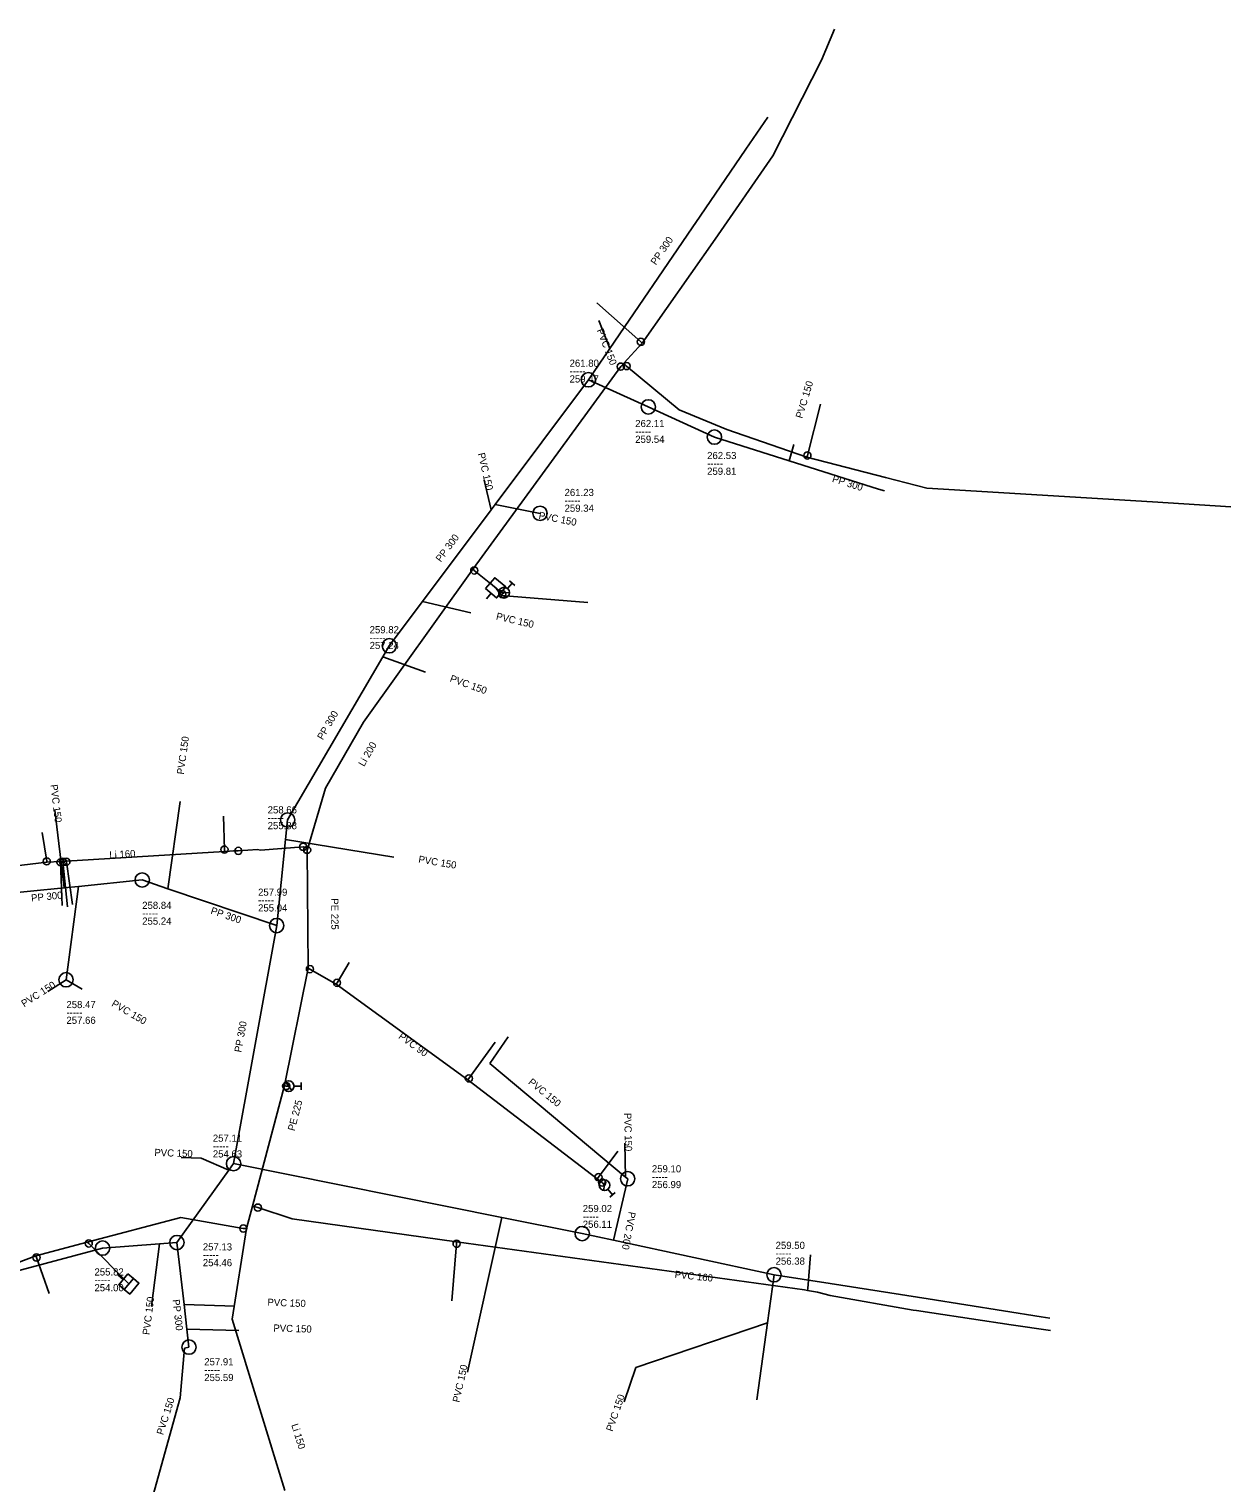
# Model space of a CAD drawing. Extents: x -771681 to -770485, y -1050143 to -1049574.
# Drawn here: x -770653 to -770485, y -1050034.6 to -1049831.5 of the extents above; entities that cross this region are included whole.
import ezdxf

# ---------------------------------------------------------------- set-up
doc = ezdxf.new("R2010")
doc.units = 0
doc.layers.add('Level 0', color=7, linetype='Continuous')

msp = doc.modelspace()

# ---------------------------------------------------------------- linework, layer by layer
at = {"layer": 'Level 0'}
for p, q in [((-770542.24, -1049835.81), (-770540.44, -1049831.47)), ((-770549.05, -1049849.2), (-770542.24, -1049835.81)), ((-770549.73, -1049843.76), (-770552.8, -1049848.25)), ((-770552.8, -1049848.25), (-770559.19, -1049857.6)), ((-770557.11, -1049860.82), (-770549.05, -1049849.2)), ((-770559.19, -1049857.6), (-770560.31, -1049859.24)), ((-770560.31, -1049859.24), (-770571.84, -1049876.11)), ((-770567.28, -1049875.34), (-770557.11, -1049860.82)), ((-770567.48, -1049875.17), (-770573.64, -1049869.74)), ((-770571.84, -1049876.11), (-770573.37, -1049872.19)), ((-770569.87, -1049878.17), (-770567.28, -1049875.34)), ((-770567.28, -1049875.34), (-770567.48, -1049875.17)), ((-770571.84, -1049876.11), (-770574.82, -1049880.47)), ((-770590.92, -1049906.89), (-770570.29, -1049878.63)), ((-770570.29, -1049878.63), (-770569.87, -1049878.17)), ((-770569.87, -1049878.17), (-770569.47, -1049878.55)), ((-770569.47, -1049878.55), (-770562.12, -1049884.66)), ((-770574.82, -1049880.47), (-770587.86, -1049897.9)), ((-770566.44, -1049884.26), (-770574.82, -1049880.47)), ((-770557.2, -1049888.48), (-770566.44, -1049884.26)), ((-770562.12, -1049884.66), (-770555.49, -1049887.4)), ((-770544.21, -1049891.04), (-770542.38, -1049883.87)), ((-770555.49, -1049887.4), (-770544.27, -1049891.28)), ((-770546.78, -1049891.78), (-770557.2, -1049888.48)), ((-770546.78, -1049891.78), (-770546.09, -1049889.5)), ((-770544.27, -1049891.28), (-770544.21, -1049891.04)), ((-770544.27, -1049891.28), (-770533.28, -1049894.12)), ((-770534.27, -1049895.74), (-770546.78, -1049891.78)), ((-770588.42, -1049898.65), (-770589.39, -1049894.48)), ((-770533.28, -1049894.12), (-770527.52, -1049895.6)), ((-770527.52, -1049895.6), (-770496.01, -1049897.54)), ((-770533.45, -1049896), (-770534.27, -1049895.74)), ((-770496.01, -1049897.54), (-770485.03, -1049898.21)), ((-770588.42, -1049898.65), (-770598, -1049911.45)), ((-770587.86, -1049897.9), (-770588.42, -1049898.65)), ((-770587.86, -1049897.9), (-770581.57, -1049899.13)), ((-770606.25, -1049928.29), (-770590.92, -1049906.89)), ((-770590.92, -1049906.89), (-770590.76, -1049907.11)), ((-770590.76, -1049907.11), (-770587.77, -1049909.53)), ((-770587.77, -1049909.53), (-770587.01, -1049910.63)), ((-770586.11, -1049909.64), (-770585.47, -1049908.87)), ((-770585.85, -1049908.55), (-770585.08, -1049909.19)), ((-770598, -1049911.45), (-770602.63, -1049917.64)), ((-770598, -1049911.45), (-770591.23, -1049913.04)), ((-770589.06, -1049911.06), (-770588.41, -1049910.3)), ((-770587.34, -1049910.19), (-770585.84, -1049910.24)), ((-770587.01, -1049910.63), (-770586.85, -1049910.42)), ((-770587.01, -1049910.63), (-770574.88, -1049911.6)), ((-770586.85, -1049910.42), (-770586.59, -1049910.21)), ((-770602.63, -1049917.64), (-770603.53, -1049919.18)), ((-770603.53, -1049919.18), (-770616.84, -1049941.97)), ((-770603.53, -1049919.18), (-770597.56, -1049921.34)), ((-770611.57, -1049937.55), (-770606.25, -1049928.29)), ((-770614.04, -1049945.91), (-770611.57, -1049937.55)), ((-770633.56, -1049951.58), (-770631.87, -1049939.4)), ((-770648.08, -1049951.45), (-770649.37, -1049940.61)), ((-770625.67, -1049946.11), (-770625.8, -1049941.44)), ((-770616.84, -1049941.97), (-770617.12, -1049944.68)), ((-770650.5, -1049947.75), (-770651.12, -1049943.73)), ((-770647.77, -1049947.71), (-770625.66, -1049946.38)), ((-770625.66, -1049946.38), (-770625.67, -1049946.11)), ((-770625.66, -1049946.38), (-770624.98, -1049946.34)), ((-770624.98, -1049946.34), (-770624.42, -1049946.27)), ((-770624.42, -1049946.27), (-770623.73, -1049946.29)), ((-770623.73, -1049946.29), (-770621.03, -1049946.11)), ((-770621.03, -1049946.11), (-770620.63, -1049946.19)), ((-770620.63, -1049946.19), (-770614.67, -1049945.73)), ((-770617.12, -1049944.68), (-770618.37, -1049956.73)), ((-770617.12, -1049944.68), (-770601.98, -1049947.19)), ((-770614.67, -1049945.73), (-770614.04, -1049945.91)), ((-770614.12, -1049946.17), (-770614.04, -1049945.91)), ((-770613.96, -1049962.67), (-770614.12, -1049946.17)), ((-770661, -1049949.12), (-770650.48, -1049947.87)), ((-770650.48, -1049947.87), (-770650.5, -1049947.75)), ((-770650.48, -1049947.87), (-770648.58, -1049947.76)), ((-770648.58, -1049947.76), (-770648.24, -1049947.74)), ((-770648.58, -1049947.76), (-770648.57, -1049947.89)), ((-770648.57, -1049947.89), (-770648.36, -1049953.91)), ((-770648.24, -1049947.74), (-770647.77, -1049947.71)), ((-770648.24, -1049947.74), (-770648.23, -1049947.83)), ((-770648.23, -1049947.83), (-770647.62, -1049954.09)), ((-770647.77, -1049947.71), (-770647.75, -1049947.81)), ((-770647.75, -1049947.81), (-770646.88, -1049953.78)), ((-770646.06, -1049951.25), (-770637.16, -1049950.36)), ((-770637.16, -1049950.36), (-770633.56, -1049951.58)), ((-770660.54, -1049952.69), (-770648.08, -1049951.45)), ((-770648.08, -1049951.45), (-770646.06, -1049951.25)), ((-770646.06, -1049951.25), (-770647.8, -1049964.3)), ((-770633.56, -1049951.58), (-770618.37, -1049956.73)), ((-770618.37, -1049956.73), (-770624.4, -1049989.99)), ((-770617.29, -1049979.08), (-770613.96, -1049962.67)), ((-770613.72, -1049962.81), (-770613.96, -1049962.67)), ((-770609.94, -1049964.72), (-770608.26, -1049961.89)), ((-770647.8, -1049964.3), (-770650.35, -1049965.93)), ((-770647.8, -1049964.3), (-770645.57, -1049965.6)), ((-770610.06, -1049964.93), (-770613.72, -1049962.81)), ((-770610.06, -1049964.93), (-770609.94, -1049964.72)), ((-770591.65, -1049978.28), (-770610.06, -1049964.93)), ((-770588.6, -1049976.01), (-770586.04, -1049972.28)), ((-770591.51, -1049978.08), (-770587.85, -1049973)), ((-770569.61, -1049991.86), (-770588.6, -1049976.01)), ((-770617.15, -1049978.58), (-770616.23, -1049979.76)), ((-770614.94, -1049978.67), (-770614.94, -1049979.67)), ((-770591.65, -1049978.28), (-770591.51, -1049978.08)), ((-770573.57, -1049992.1), (-770591.65, -1049978.28)), ((-770621.77, -1049995.92), (-770617.29, -1049979.08)), ((-770617.29, -1049979.08), (-770617.04, -1049979.15)), ((-770617.04, -1049979.15), (-770616.69, -1049979.17)), ((-770615.94, -1049979.17), (-770614.94, -1049979.17)), ((-770628.94, -1049989.21), (-770631.71, -1049989.11)), ((-770573.41, -1049991.89), (-770570.71, -1049988.23)), ((-770569.61, -1049991.86), (-770569.73, -1049987.13)), ((-770625.07, -1049990.92), (-770632.31, -1050001.01)), ((-770625.07, -1049990.92), (-770628.94, -1049989.21)), ((-770624.4, -1049989.99), (-770625.07, -1049990.92)), ((-770586.89, -1049997.51), (-770624.4, -1049989.99)), ((-770573.57, -1049992.1), (-770573.41, -1049991.89)), ((-770572.88, -1049992.63), (-770573.57, -1049992.1)), ((-770572.56, -1049993), (-770572.88, -1049992.63)), ((-770572.41, -1049992.27), (-770572.72, -1049993.74)), ((-770571.29, -1050000.7), (-770569.32, -1049992.1)), ((-770569.32, -1049992.1), (-770569.61, -1049991.86)), ((-770572.08, -1049993.57), (-770571.44, -1049994.34)), ((-770571.05, -1049994.02), (-770571.82, -1049994.66)), ((-770622.6, -1049999.04), (-770621.77, -1049995.92)), ((-770621, -1049996.13), (-770621.77, -1049995.92)), ((-770616.2, -1049997.69), (-770621, -1049996.13)), ((-770644.83, -1050000.94), (-770631.77, -1049997.52)), ((-770631.77, -1049997.52), (-770623.03, -1049999.05)), ((-770624.58, -1050011.72), (-770622.6, -1049999.04)), ((-770623.03, -1049999.05), (-770622.6, -1049999.04)), ((-770593.24, -1050000.93), (-770616.2, -1049997.69)), ((-770586.89, -1049997.51), (-770591.7, -1050019.14)), ((-770575.68, -1049999.76), (-770586.89, -1049997.51)), ((-770652.02, -1050002.86), (-770644.83, -1050000.94)), ((-770644.63, -1050001.14), (-770644.83, -1050000.94)), ((-770639.03, -1050006.8), (-770644.63, -1050001.14)), ((-770634.75, -1050001.19), (-770642.7, -1050001.79)), ((-770634.75, -1050001.19), (-770635.84, -1050009.91)), ((-770632.31, -1050001.01), (-770634.75, -1050001.19)), ((-770631.32, -1050009.65), (-770632.31, -1050001.01)), ((-770593.23, -1050001.19), (-770593.88, -1050009.16)), ((-770593.24, -1050000.93), (-770593.23, -1050001.19)), ((-770544.62, -1050007.62), (-770593.24, -1050000.93)), ((-770571.29, -1050000.7), (-770575.68, -1049999.76)), ((-770548.87, -1050005.52), (-770571.29, -1050000.7)), ((-770677.84, -1050012.6), (-770652.02, -1050002.86)), ((-770642.7, -1050001.79), (-770654.72, -1050005)), ((-770652.02, -1050002.86), (-770651.93, -1050003.1)), ((-770651.93, -1050003.1), (-770650.15, -1050008.15)), ((-770544.16, -1050007.45), (-770543.78, -1050002.72)), ((-770640.56, -1050005.51), (-770639.8, -1050006.16)), ((-770549.8, -1050012.23), (-770548.87, -1050005.52)), ((-770541.02, -1050006.75), (-770548.87, -1050005.52)), ((-770527.35, -1050008.9), (-770541.02, -1050006.75)), ((-770544.18, -1050007.7), (-770544.62, -1050007.62)), ((-770544.18, -1050007.7), (-770544.16, -1050007.45)), ((-770542.82, -1050007.96), (-770544.18, -1050007.7)), ((-770541.02, -1050008.43), (-770542.82, -1050007.96)), ((-770529.43, -1050010.45), (-770541.02, -1050008.43)), ((-770511.54, -1050011.38), (-770527.35, -1050008.9)), ((-770630.92, -1050013.1), (-770631.32, -1050009.65)), ((-770631.32, -1050009.65), (-770624.24, -1050009.89)), ((-770528.98, -1050010.52), (-770529.43, -1050010.45)), ((-770526.84, -1050010.84), (-770528.98, -1050010.52)), ((-770515.73, -1050012.51), (-770526.84, -1050010.84)), ((-770510.33, -1050011.57), (-770511.54, -1050011.38)), ((-770630.63, -1050015.63), (-770630.92, -1050013.1)), ((-770630.92, -1050013.1), (-770623.68, -1050013.31)), ((-770617.23, -1050035.68), (-770624.58, -1050011.72)), ((-770549.8, -1050012.23), (-770568.18, -1050018.47)), ((-770551.29, -1050022.97), (-770549.8, -1050012.23)), ((-770510.25, -1050013.31), (-770515.73, -1050012.51)), ((-770631.25, -1050015.79), (-770631.87, -1050022.72)), ((-770630.63, -1050015.63), (-770631.25, -1050015.79)), ((-770568.18, -1050018.47), (-770569.83, -1050023.26)), ((-770631.87, -1050022.72), (-770636.39, -1050038.95))]:
    msp.add_line(p, q, dxfattribs=at)
for points in [[(-770589.18, -1049909.65), (-770587.65, -1049910.94), (-770587, -1049910.17), (-770588.54, -1049908.89)], [(-770639.15, -1050005.39), (-770640.44, -1050006.92), (-770639.67, -1050007.57), (-770638.39, -1050006.03)]]:
    msp.add_lwpolyline(points, close=True, dxfattribs=at)
for points in [[(-770588.54, -1049908.89), (-770587.89, -1049908.12), (-770586.36, -1049909.41), (-770587, -1049910.17)], [(-770638.39, -1050006.03), (-770637.62, -1050006.68), (-770638.91, -1050008.21), (-770639.67, -1050007.57)]]:
    msp.add_lwpolyline(points, dxfattribs=at)
for centre, radius in [((-770567.48, -1049875.17), 0.5), ((-770570.29, -1049878.63), 0.5), ((-770569.47, -1049878.55), 0.5), ((-770574.82, -1049880.47), 1), ((-770566.44, -1049884.26), 1), ((-770557.2, -1049888.48), 1), ((-770544.21, -1049891.04), 0.5), ((-770581.57, -1049899.13), 1), ((-770590.76, -1049907.11), 0.5), ((-770586.59, -1049910.21), 0.75), ((-770586.85, -1049910.42), 0.5), ((-770602.63, -1049917.64), 1), ((-770616.84, -1049941.97), 1), ((-770625.67, -1049946.11), 0.5), ((-770623.73, -1049946.29), 0.5), ((-770614.67, -1049945.73), 0.5), ((-770614.12, -1049946.17), 0.5), ((-770650.5, -1049947.75), 0.5), ((-770648.57, -1049947.89), 0.5), ((-770648.23, -1049947.83), 0.5), ((-770647.75, -1049947.81), 0.5), ((-770637.16, -1049950.36), 1), ((-770618.37, -1049956.73), 1), ((-770613.72, -1049962.81), 0.5), ((-770647.8, -1049964.3), 1), ((-770609.94, -1049964.72), 0.5), ((-770617.04, -1049979.15), 0.5), ((-770616.69, -1049979.17), 0.75), ((-770591.51, -1049978.08), 0.5), ((-770624.4, -1049989.99), 1), ((-770569.32, -1049992.1), 1), ((-770573.41, -1049991.89), 0.5), ((-770572.88, -1049992.63), 0.5), ((-770572.56, -1049993), 0.75), ((-770621, -1049996.13), 0.5), ((-770623.03, -1049999.05), 0.5), ((-770575.68, -1049999.76), 1), ((-770644.63, -1050001.14), 0.5), ((-770642.7, -1050001.79), 1), ((-770632.31, -1050001.01), 1), ((-770593.23, -1050001.19), 0.5), ((-770651.93, -1050003.1), 0.5), ((-770548.87, -1050005.52), 1), ((-770630.63, -1050015.63), 1)]:
    msp.add_circle(centre, radius, dxfattribs=at)

# ---------------------------------------------------------------- texts
for s, rotation, p in [('PP 300', 55.67, (-770565.38, -1049864.52)), ('PVC 150', 291.321, (-770573.67, -1049873.55)), ('PVC 150', 73.163, (-770544.93, -1049885.94)), ('PVC 150', 283.095, (-770590.28, -1049890.79)), ('PP 300', 342.435, (-770540.83, -1049894.71)), ('PVC 150', 348.936, (-770581.82, -1049899.87)), ('PP 300', 53.187, (-770595.44, -1049906.02)), ('PVC 150', 346.783, (-770587.78, -1049913.95)), ('PVC 150', 340.109, (-770594.25, -1049922.6)), ('PP 300', 59.714, (-770611.92, -1049930.87)), ('PVC 150', 82.101, (-770631.35, -1049935.66)), ('Li 200', 60.122, (-770606.16, -1049934.59)), ('PVC 150', 276.786, (-770649.99, -1049937.07)), ('Li 160', 3.313, (-770641.72, -1049947.35)), ('PVC 150', 350.587, (-770598.62, -1049947.92)), ('PP 300', 5.654, (-770652.63, -1049953.38)), ('PP 300', 341.279, (-770627.68, -1049955.05)), ('PE 225', 270.556, (-770610.76, -1049952.93)), ('PVC 150', 32.587, (-770653.66, -1049968.16)), ('PVC 150', 329.76, (-770641.54, -1049967.91)), ('PP 300', 79.724, (-770623.32, -1049974.5)), ('PVC 90', 324.052, (-770601.44, -1049972.41)), ('PVC 150', 320.755, (-770583.3, -1049978.75)), ('PE 225', 75.102, (-770615.88, -1049985.49)), ('PVC 150', 271.453, (-770569.82, -1049982.92)), ('PVC 150', 357.932, (-770635.47, -1049988.91)), ('PVC 200', 259.428, (-770569.17, -1049996.65)), ('PVC 160', 354, (-770562.79, -1050005.93)), ('PVC 150', 82.875, (-770636.14, -1050013.96)), ('PP 300', 276.613, (-770632.93, -1050009.01)), ('PVC 150', 358.059, (-770619.67, -1050009.85)), ('PVC 150', 358.339, (-770618.84, -1050013.45)), ('PVC 150', 77.463, (-770592.84, -1050023.42)), ('PVC 150', 72.247, (-770634.24, -1050027.97)), ('PVC 150', 70.993, (-770571.44, -1050027.49)), ('Li 150', 287.054, (-770616.34, -1050026.49))]:
    msp.add_text(s, height=1, rotation=rotation, dxfattribs=at).set_placement(p)
for s, p in [('-----', (-770577.44, -1049879.75)), ('261.80', (-770577.44, -1049878.65)), ('259.47', (-770577.44, -1049880.85)), ('262.11', (-770568.27, -1049887.08)), ('-----', (-770568.27, -1049888.18)), ('259.54', (-770568.27, -1049889.28)), ('262.53', (-770558.22, -1049891.55)), ('-----', (-770558.22, -1049892.65)), ('259.81', (-770558.22, -1049893.75)), ('-----', (-770578.14, -1049897.81)), ('261.23', (-770578.14, -1049896.71)), ('259.34', (-770578.14, -1049898.91)), ('259.82', (-770605.38, -1049915.89)), ('-----', (-770605.38, -1049916.99)), ('257.24', (-770605.38, -1049918.09)), ('258.66', (-770619.63, -1049941.06)), ('-----', (-770619.63, -1049942.16)), ('255.88', (-770619.63, -1049943.26)), ('257.99', (-770620.97, -1049952.56)), ('258.84', (-770637.16, -1049954.4)), ('-----', (-770620.97, -1049953.66)), ('255.04', (-770620.97, -1049954.76)), ('-----', (-770637.16, -1049955.5)), ('255.24', (-770637.16, -1049956.6)), ('258.47', (-770647.75, -1049968.26)), ('-----', (-770647.75, -1049969.36)), ('257.66', (-770647.75, -1049970.46)), ('257.11', (-770627.29, -1049986.93)), ('-----', (-770627.29, -1049988.03)), ('254.63', (-770627.29, -1049989.13)), ('259.10', (-770565.94, -1049991.21)), ('-----', (-770565.94, -1049992.31)), ('256.99', (-770565.94, -1049993.41)), ('259.02', (-770575.6, -1049996.76)), ('-----', (-770575.6, -1049997.86)), ('256.11', (-770575.6, -1049998.96)), ('257.13', (-770628.69, -1050002.12)), ('259.50', (-770548.65, -1050001.91)), ('-----', (-770628.69, -1050003.22)), ('254.46', (-770628.69, -1050004.32)), ('-----', (-770548.65, -1050003.01)), ('256.38', (-770548.65, -1050004.11)), ('255.82', (-770643.83, -1050005.62)), ('-----', (-770643.83, -1050006.72)), ('254.00', (-770643.83, -1050007.82)), ('257.91', (-770628.49, -1050018.17)), ('-----', (-770628.49, -1050019.27)), ('255.59', (-770628.49, -1050020.37))]:
    msp.add_text(s, height=1, dxfattribs=at).set_placement(p)

doc.saveas('drawing.dxf')
